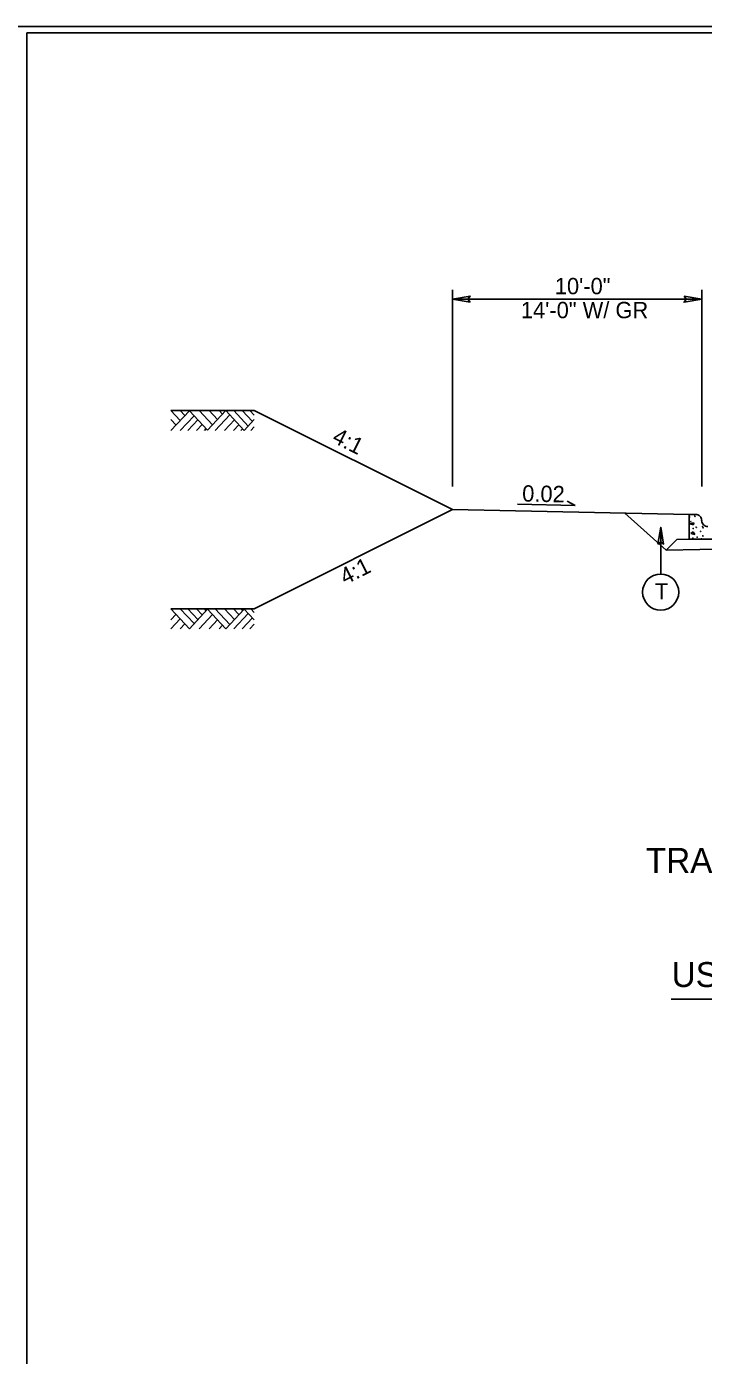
# Model space of a CAD drawing. Extents: x 1901670 to 1902225, y 193498 to 194278.
# Drawn here: x 1901982.5 to 1902009.7, y 193552.5 to 193605.8 of the extents above; entities that cross this region are included whole.
import ezdxf

# ---------------------------------------------------------------- set-up
doc = ezdxf.new("R2010")
doc.units = 0
for name, color, linetype in [('Old_Level_1', 7, 'Continuous'), ('Old_Level_11', 7, 'Continuous'), ('Old_Level_2', 7, 'Continuous'), ('Old_Level_20', 7, 'Continuous'), ('Prop Dimension', 7, 'Continuous'), ('Sheet Border Standard 30in CELL', 7, 'Continuous'), ('Sheet Plot Border Inside CELL', 7, 'Continuous'), ('Typical Curb CELL', 7, 'Continuous'), ('Typical Pavement Slope CELL', 7, 'Continuous'), ('Typical Terminator CELL', 7, 'Continuous')]:
    doc.layers.add(name, color=color, linetype=linetype)

# ---------------------------------------------------------------- blocks, each defined once
blk = doc.blocks.new('TERMINATOR')
at = {"layer": 'Typical Terminator CELL'}
blk.add_lwpolyline([(-0.469, 0.081), (0, 0), (-0.471, -0.083), (-0.411, 0)], close=True, dxfattribs=at)

msp = doc.modelspace()

# ---------------------------------------------------------------- linework, layer by layer
at = {"layer": 'Old_Level_1'}
for p, q in [((1901988.322, 193590.366), (1901988.697, 193589.963)), ((1901988.322, 193589.561), (1901989.064, 193590.358)), ((1901988.697, 193590.366), (1901988.884, 193590.165)), ((1901989.064, 193590.358), (1901989.788, 193589.579)), ((1901989.455, 193590.366), (1901989.988, 193589.793)), ((1901989.788, 193589.579), (1901990.519, 193590.365)), ((1901989.853, 193590.366), (1901990.186, 193590.007)), ((1901990.255, 193590.366), (1901990.388, 193590.223)), ((1901990.519, 193590.365), (1901991.26, 193589.569)), ((1901990.841, 193590.366), (1901991.421, 193589.743)), ((1901991.174, 193590.366), (1901991.588, 193589.922)), ((1901991.494, 193590.366), (1901991.664, 193590.183)), ((1901988.322, 193590.004), (1901988.528, 193589.782)), ((1901988.696, 193589.561), (1901989.25, 193590.157)), ((1901989.005, 193589.561), (1901989.406, 193589.99)), ((1901989.352, 193589.561), (1901989.579, 193589.804)), ((1901990.098, 193589.561), (1901990.684, 193590.189)), ((1901990.468, 193589.561), (1901990.868, 193589.99)), ((1901990.834, 193589.561), (1901991.051, 193589.794)), ((1901991.26, 193589.569), (1901991.664, 193590.004)), ((1901989.663, 193589.561), (1901989.734, 193589.637)), ((1901991.129, 193589.561), (1901991.198, 193589.635)), ((1901991.53, 193589.561), (1901991.664, 193589.704)), ((1902002.235, 193586.607), (1902004.55, 193586.558)), ((1902004.55, 193586.558), (1902004.217, 193586.725)), ((1902006.54, 193586.249), (1902008.198, 193584.765)), ((1902008.621, 193585.188), (1902008.198, 193584.765)), ((1902008.621, 193585.188), (1902009.121, 193585.198)), ((1902014.623, 193584.894), (1902008.198, 193584.765)), ((1901988.322, 193582.409), (1901989.064, 193581.612)), ((1901988.696, 193582.409), (1901989.25, 193581.813)), ((1901989.005, 193582.409), (1901989.406, 193581.98)), ((1901989.064, 193581.612), (1901989.788, 193582.391)), ((1901989.352, 193582.409), (1901989.579, 193582.166)), ((1901989.663, 193582.409), (1901989.734, 193582.333)), ((1901989.788, 193582.391), (1901990.519, 193581.605)), ((1901990.098, 193582.409), (1901990.684, 193581.781)), ((1901990.468, 193582.409), (1901990.868, 193581.98)), ((1901990.519, 193581.605), (1901991.26, 193582.401)), ((1901990.834, 193582.409), (1901991.051, 193582.176)), ((1901991.129, 193582.409), (1901991.198, 193582.335)), ((1901991.26, 193582.401), (1901991.664, 193581.966)), ((1901991.53, 193582.409), (1901991.664, 193582.266)), ((1901988.322, 193581.966), (1901988.528, 193582.188)), ((1901988.322, 193581.604), (1901988.697, 193582.007)), ((1901988.697, 193581.604), (1901988.884, 193581.805)), ((1901989.455, 193581.604), (1901989.988, 193582.177)), ((1901989.853, 193581.604), (1901990.186, 193581.963)), ((1901990.255, 193581.604), (1901990.388, 193581.747)), ((1901990.841, 193581.604), (1901991.421, 193582.227)), ((1901991.174, 193581.604), (1901991.588, 193582.048)), ((1901991.494, 193581.604), (1901991.664, 193581.787))]:
    msp.add_line(p, q, dxfattribs=at)
at = {"layer": 'Old_Level_11'}
for p, q in [((1902007.975, 193583.805), (1902007.975, 193585.679)), ((1902008.39, 193566.741), (1902029.517, 193566.741))]:
    msp.add_line(p, q, dxfattribs=at)
msp.add_lwpolyline([(1902007.859, 193585.008), (1902007.975, 193585.679), (1902008.094, 193585.004), (1902007.975, 193585.09)], close=True, dxfattribs=at)
msp.add_circle((1902007.975, 193583.08), 0.725, dxfattribs=at)
at = {"layer": 'Prop Dimension'}
for p, q in [((1901999.621, 193587.319), (1901999.621, 193595.201)), ((1902009.621, 193587.319), (1902009.621, 193595.201)), ((1901999.621, 193594.831), (1902009.621, 193594.831))]:
    msp.add_line(p, q, dxfattribs=at)
at = {"layer": 'Sheet Border Standard 30in CELL'}
msp.add_line((1901982.644, 193605.514), (1901982.644, 193605.514), dxfattribs=at)
msp.add_lwpolyline([(1902132.544, 193605.514), (1901982.544, 193605.514), (1901982.544, 193500.514), (1902132.544, 193500.514)], close=True, dxfattribs=at)
at = {"layer": 'Sheet Plot Border Inside CELL'}
msp.add_lwpolyline([(1902133.794, 193605.769), (1901967.144, 193605.769), (1901967.144, 193500.259), (1902133.794, 193500.259)], close=True, dxfattribs=at)
at = {"layer": 'Typical Curb CELL'}
for p, q in [((1902009.121, 193585.198), (1902009.121, 193586.198)), ((1902009.121, 193586.198), (1902009.381, 193586.198)), ((1902009.157, 193585.82), (1902009.312, 193585.864)), ((1902009.295, 193585.774), (1902009.157, 193585.82)), ((1902009.283, 193585.501), (1902009.18, 193585.426)), ((1902009.346, 193585.386), (1902009.283, 193585.501)), ((1902009.312, 193585.864), (1902009.295, 193585.774)), ((1902009.621, 193585.948), (1902009.621, 193585.958)), ((1902009.121, 193585.198), (1902011.621, 193585.198)), ((1902009.18, 193585.426), (1902009.346, 193585.386))]:
    msp.add_line(p, q, dxfattribs=at)
for centre in [(1902009.134, 193586.088), (1902009.351, 193586.122), (1902009.186, 193585.905), (1902009.283, 193585.632), (1902009.403, 193585.682), (1902009.58, 193585.518), (1902009.66, 193585.711), (1902009.677, 193585.661), (1902009.266, 193585.244), (1902009.437, 193585.284), (1902009.614, 193585.221), (1902009.671, 193585.335)]:
    msp.add_circle(centre, 0.00802, dxfattribs=at)
for centre, start, end in [((1902009.381, 193585.958), 0.0002, 90.0002), ((1902009.86, 193585.948), 180.0002, 272.3846)]:
    msp.add_arc(centre, 0.24, start, end, dxfattribs=at)
at = {"layer": 'Typical Pavement Slope CELL'}
for p in [(1901991.664, 193590.366), (1901991.664, 193582.409), (1902009.121, 193586.198)]:
    msp.add_line(p, (1901999.621, 193586.388), dxfattribs=at)
for points in [[(1901988.322, 193590.366), (1901991.664, 193590.366)], [(1901988.322, 193582.409), (1901991.664, 193582.409)]]:
    msp.add_lwpolyline(points, dxfattribs=at)

# ---------------------------------------------------------------- block references
at = {"layer": 'Prop Dimension', "xscale": 1.5, "yscale": 1.5, "rotation": 180}
msp.add_blockref('TERMINATOR', (1901999.621, 193594.831), dxfattribs=at)
at = {"layer": 'Prop Dimension', "xscale": 1.5, "yscale": 1.5}
msp.add_blockref('TERMINATOR', (1902009.621, 193594.831), dxfattribs=at)

# ---------------------------------------------------------------- texts
at = {"layer": 'Old_Level_1'}
for rotation, p in [(333.4349, (1901994.746, 193589.115)), (26.5651, (1901995.312, 193583.36))]:
    msp.add_text('4:1', height=0.656, rotation=rotation, dxfattribs=at).set_placement(p)
at = {"layer": 'Old_Level_11'}
for s, p in [('TRANSITION FROM EXISTING TO TYPICAL SECTION NO. 12', (1902007.378, 193571.814)), ('USE TYPICAL SECTION NO.  12:', (1902008.415, 193567.235))]:
    msp.add_text(s, height=1, dxfattribs=at).set_placement(p)
at = {"layer": 'Old_Level_2'}
msp.add_text('0.02', height=0.656, rotation=358.8084, dxfattribs=at).set_placement((1902002.412, 193586.714))
at = {"layer": 'Old_Level_20'}
msp.add_text('T', height=0.649, dxfattribs=at).set_placement((1902007.747, 193582.787))
at = {"layer": 'Prop Dimension'}
for s, p in [('10\'-0" ', (1902003.727, 193595.029)), ('14\'-0" W/ GR ', (1902002.365, 193594.068))]:
    msp.add_text(s, height=0.656, dxfattribs=at).set_placement(p)

doc.saveas('drawing.dxf')
